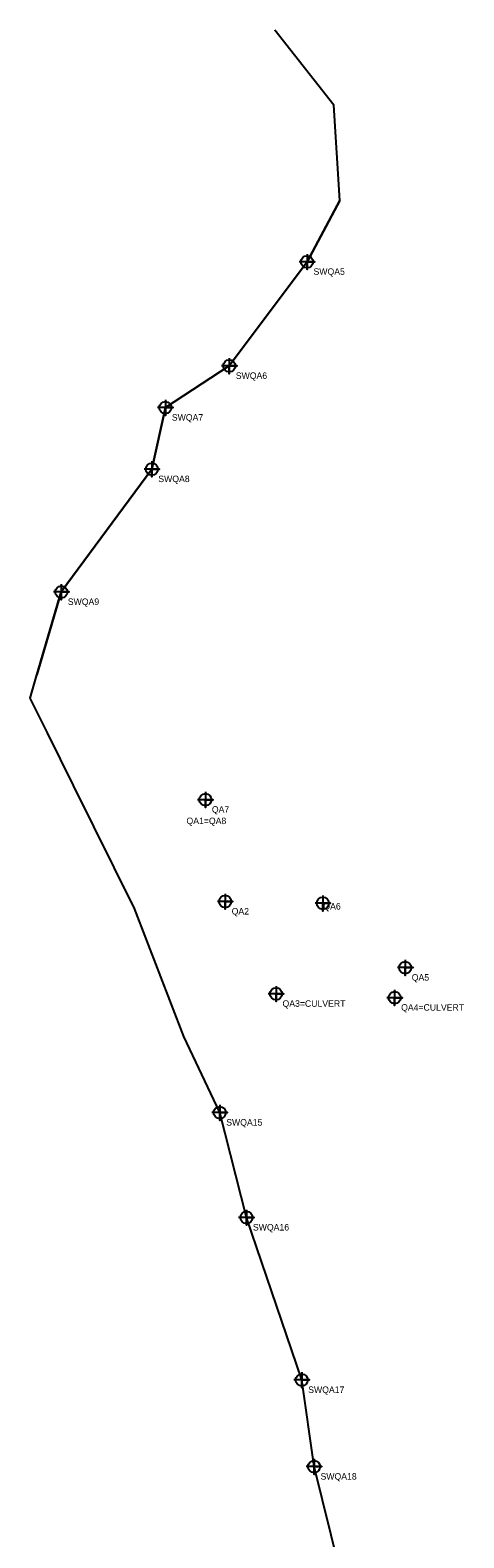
# Model space of a CAD drawing. Extents: x 1705487 to 1707934, y 819100 to 822252.
# Drawn here: x 1705487 to 1705654, y 821672 to 822252 of the extents above; entities that cross this region are included whole.
import ezdxf

# ---------------------------------------------------------------- set-up
doc = ezdxf.new("R2010")
doc.units = 0
for name, color, linetype in [('Exist Hydro Jurisdictional Stream or Body of Water NEU Mitigable', 7, 'Continuous'), ('Exist Hydro Jurisdictional Stream or Body of Water NEU Mitigable Cogo Comment', 7, 'Continuous'), ('Exist Hydro Jurisdictional Stream or Body of Water NEU Mitigable Cogo Point CELL', 7, 'Continuous'), ('Exist Hydro Jurisdictional Stream or Body of Water NEU NonMitigable Cogo Comment', 7, 'Continuous'), ('Exist Hydro Jurisdictional Stream or Body of Water NonMitigable', 7, 'Continuous')]:
    doc.layers.add(name, color=color, linetype=linetype)

msp = doc.modelspace()

# ---------------------------------------------------------------- linework, layer by layer
at = {"layer": 'Exist Hydro Jurisdictional Stream or Body of Water NEU Mitigable'}
msp.add_lwpolyline([(1705606.05, 822186.61), (1705593.47, 822163.01), (1705563.53, 822122.94), (1705538.89, 822106.87), (1705533.68, 822083.21), (1705498.81, 822035.91), (1705489.34, 822003.98)], dxfattribs=at)
at = {"layer": 'Exist Hydro Jurisdictional Stream or Body of Water NEU Mitigable Cogo Point CELL'}
for points in [[(1705593.47, 822166.01), (1705593.47, 822160.01), (1705593.47, 822163.01), (1705596.47, 822163.01), (1705590.47, 822163.01)], [(1705563.53, 822125.94), (1705563.53, 822119.94), (1705563.53, 822122.94), (1705566.53, 822122.94), (1705560.53, 822122.94)], [(1705538.89, 822109.87), (1705538.89, 822103.87), (1705538.89, 822106.87), (1705541.89, 822106.87), (1705535.89, 822106.87)], [(1705533.68, 822086.21), (1705533.68, 822080.21), (1705533.68, 822083.21), (1705536.68, 822083.21), (1705530.68, 822083.21)], [(1705498.81, 822038.91), (1705498.81, 822032.91), (1705498.81, 822035.91), (1705501.81, 822035.91), (1705495.81, 822035.91)], [(1705559.84, 821838.47), (1705559.84, 821832.47), (1705559.84, 821835.47), (1705562.84, 821835.47), (1705556.84, 821835.47)], [(1705570.13, 821798.08), (1705570.13, 821792.08), (1705570.13, 821795.08), (1705573.13, 821795.08), (1705567.13, 821795.08)], [(1705591.42, 821735.54), (1705591.42, 821729.54), (1705591.42, 821732.54), (1705594.42, 821732.54), (1705588.42, 821732.54)], [(1705596.17, 821702.17), (1705596.17, 821696.17), (1705596.17, 821699.17), (1705599.17, 821699.17), (1705593.17, 821699.17)]]:
    msp.add_lwpolyline(points, dxfattribs=at)
for centre in [(1705593.47, 822163.01), (1705563.53, 822122.94), (1705538.89, 822106.87), (1705533.68, 822083.21), (1705498.81, 822035.91), (1705559.84, 821835.47), (1705570.13, 821795.08), (1705591.42, 821732.54), (1705596.17, 821699.17)]:
    msp.add_circle(centre, 2.34, dxfattribs=at)
at = {"layer": 'Exist Hydro Jurisdictional Stream or Body of Water NEU NonMitigable Cogo Comment'}
for points in [[(1705554.31, 821958.94), (1705554.31, 821952.94), (1705554.31, 821955.94), (1705557.31, 821955.94), (1705551.31, 821955.94)], [(1705561.94, 821919.74), (1705561.94, 821913.74), (1705561.94, 821916.74), (1705564.94, 821916.74), (1705558.94, 821916.74)], [(1705599.56, 821919.07), (1705599.56, 821913.07), (1705599.56, 821916.07), (1705602.56, 821916.07), (1705596.56, 821916.07)], [(1705631.31, 821894.28), (1705631.31, 821888.28), (1705631.31, 821891.28), (1705634.31, 821891.28), (1705628.31, 821891.28)], [(1705581.53, 821884.21), (1705581.53, 821878.21), (1705581.53, 821881.21), (1705584.53, 821881.21), (1705578.53, 821881.21)], [(1705627.22, 821882.72), (1705627.22, 821876.72), (1705627.22, 821879.72), (1705630.22, 821879.72), (1705624.22, 821879.72)]]:
    msp.add_lwpolyline(points, dxfattribs=at)
for centre in [(1705554.31, 821955.94), (1705561.94, 821916.74), (1705599.56, 821916.07), (1705631.31, 821891.28), (1705581.53, 821881.21), (1705627.22, 821879.72)]:
    msp.add_circle(centre, 2.34, dxfattribs=at)
at = {"layer": 'Exist Hydro Jurisdictional Stream or Body of Water NonMitigable'}
msp.add_lwpolyline([(1705619.1, 821606.91), (1705596.17, 821699.17), (1705591.42, 821732.54), (1705570.13, 821795.08), (1705559.84, 821835.47), (1705545.95, 821864.72), (1705527.05, 821914.05), (1705503.55, 821961.36), (1705493.44, 821981.71), (1705486.8, 821995.09), (1705489.34, 822003.98), (1705498.81, 822035.91), (1705533.68, 822083.21), (1705538.89, 822106.87), (1705563.53, 822122.94), (1705593.47, 822163.01), (1705606.05, 822186.61), (1705603.81, 822223.32), (1705581.04, 822252.21), (1705581.04, 822252.21)], dxfattribs=at)

# ---------------------------------------------------------------- texts
at = {"layer": 'Exist Hydro Jurisdictional Stream or Body of Water NEU Mitigable Cogo Comment'}
for s, p in [('SWQA5', (1705595.97, 822158.01)), ('SWQA6', (1705566.03, 822117.94)), ('SWQA7', (1705541.39, 822101.87)), ('SWQA8', (1705536.18, 822078.21)), ('SWQA9', (1705501.31, 822030.91)), ('SWQA15', (1705562.34, 821830.47)), ('SWQA16', (1705572.63, 821790.08)), ('SWQA17', (1705593.92, 821727.54)), ('SWQA18', (1705598.67, 821694.17))]:
    msp.add_text(s, height=2.5, dxfattribs=at).set_placement(p)
at = {"layer": 'Exist Hydro Jurisdictional Stream or Body of Water NEU NonMitigable Cogo Comment'}
for s, p in [('QA7', (1705556.81, 821950.94)), ('QA1=QA8', (1705547.03, 821946.54)), ('QA6', (1705599.76, 821913.64)), ('QA2', (1705564.44, 821911.74)), ('QA5', (1705633.81, 821886.28)), ('QA3=CULVERT', (1705584.03, 821876.21)), ('QA4=CULVERT', (1705629.72, 821874.72))]:
    msp.add_text(s, height=2.5, dxfattribs=at).set_placement(p)

doc.saveas('drawing.dxf')
